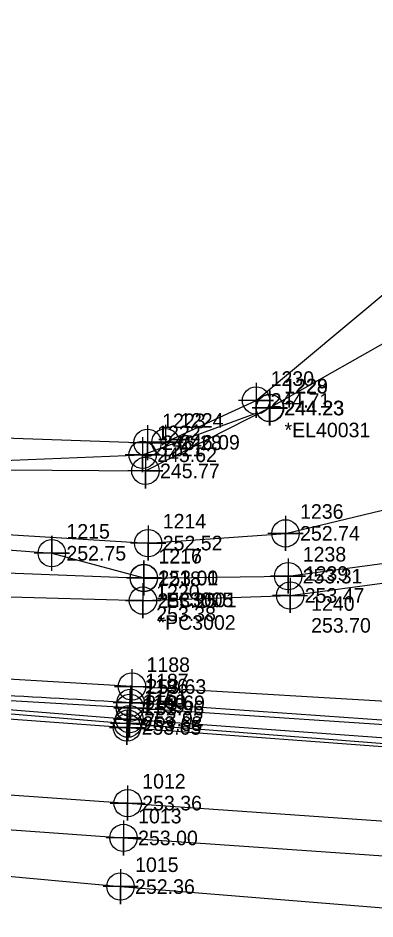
# Model space of a CAD drawing. Extents: x 2130962 to 2131465, y 643052 to 644206.
# Drawn here: x 2131077.2 to 2131138.3, y 643151.7 to 643306.2 of the extents above; entities that cross this region are included whole.
import ezdxf

# ---------------------------------------------------------------- set-up
doc = ezdxf.new("R2010")
doc.units = 0
for name, color, linetype in [('Exist DTM Breakline', 7, 'Continuous'), ('Exist DTM Breakline Cogo Elevation', 7, 'Continuous'), ('Exist DTM Breakline Cogo Number', 7, 'Continuous'), ('Exist DTM Breakline Cogo Point CELL', 7, 'Continuous'), ('Exist DTM Drainline', 7, 'Continuous'), ('Exist DTM Drainline Cogo Comment', 7, 'Continuous'), ('Exist DTM Drainline Cogo Elevation', 7, 'Continuous'), ('Exist DTM Drainline Cogo Number', 7, 'Continuous'), ('Exist DTM Drainline Cogo Point CELL', 7, 'Continuous'), ('Exist Roads Curbs', 7, 'Continuous'), ('Exist Roads Curbs Cogo Elevation', 7, 'Continuous'), ('Exist Roads Curbs Cogo Number', 7, 'Continuous'), ('Exist Roads Curbs Cogo Point CELL', 7, 'Continuous'), ('Exist Roads EOP', 7, 'Continuous'), ('Exist Roads EOP Cogo Comment', 7, 'Continuous'), ('Exist Roads EOP Cogo Elevation', 7, 'Continuous'), ('Exist Roads EOP Cogo Number', 7, 'Continuous'), ('Exist Roads EOP Cogo Point CELL', 7, 'Continuous'), ('Exist Roads EOT', 7, 'Continuous'), ('Exist Roads EOT Cogo Comment', 7, 'Continuous'), ('Exist Roads EOT Cogo Elevation', 7, 'Continuous'), ('Exist Roads EOT Cogo Number', 7, 'Continuous'), ('Exist Roads EOT Cogo Point CELL', 7, 'Continuous'), ('Exist Roads Soil', 7, 'Continuous'), ('Exist Roads Soil Cogo Comment', 7, 'Continuous'), ('Exist Roads Soil Cogo Elevation', 7, 'Continuous'), ('Exist Roads Soil Cogo Number', 7, 'Continuous'), ('Exist Roads Soil Cogo Point CELL', 7, 'Continuous')]:
    doc.layers.add(name, color=color, linetype=linetype)

msp = doc.modelspace()

# ---------------------------------------------------------------- linework, layer by layer
at = {"layer": 'Exist DTM Breakline'}
for points in [[(2131000.7408, 643235.0731), (2131050.2503, 643235.0771), (2131099.3971, 643233.3967), (2131102.4734, 643233.467), (2131117.9784, 643240.6457), (2131141.4902, 643260.2289), (2131148.9668, 643267.309), (2131161.3925, 643274.3195), (2131169.1458, 643283.2692), (2131172.0772, 643292.493), (2131174.434, 643316.7319), (2131174.0607, 643347.0813), (2131174.2633, 643367.3367), (2131180.4607, 643413.966), (2131183.0424, 643464.7744), (2131179.7562, 643510.5479), (2131157.5016, 643561.2065), (2131139.0887, 643604.6918), (2131124.996, 643650.6897)], [(2131000.2707, 643222.2884), (2131049.3172, 643219.2511), (2131099.5024, 643216.1866), (2131123.0232, 643217.8518), (2131146.7721, 643223.5416), (2131166.8509, 643229.4959), (2131199.4918, 643255.6512), (2131208.4065, 643272.9132), (2131217.3052, 643317.6851), (2131214.0619, 643367.4973), (2131211.0353, 643416.1836)], [(2130997.5489, 643165.941), (2131045.6664, 643161.7962), (2131094.7686, 643157.2786), (2131146.0902, 643153.1147), (2131194.5413, 643146.0346), (2131212.7846, 643137.5737), (2131227.5943, 643121.2545), (2131235.8712, 643098.3644), (2131243.3589, 643075.7514)]]:
    msp.add_lwpolyline(points, dxfattribs=at)
at = {"layer": 'Exist DTM Breakline Cogo Point CELL'}
for points in [[(2131117.9784, 643243.6457), (2131117.9784, 643237.6457), (2131117.9784, 643240.6457), (2131120.9784, 643240.6457), (2131114.9784, 643240.6457)], [(2131099.3971, 643236.3967), (2131099.3971, 643230.3967), (2131099.3971, 643233.3967), (2131102.3971, 643233.3967), (2131096.3971, 643233.3967)], [(2131102.4734, 643236.467), (2131102.4734, 643230.467), (2131102.4734, 643233.467), (2131105.4734, 643233.467), (2131099.4734, 643233.467)], [(2131123.0232, 643220.8518), (2131123.0232, 643214.8518), (2131123.0232, 643217.8518), (2131126.0232, 643217.8518), (2131120.0232, 643217.8518)], [(2131099.5024, 643219.1866), (2131099.5024, 643213.1866), (2131099.5024, 643216.1866), (2131102.5024, 643216.1866), (2131096.5024, 643216.1866)], [(2131094.7686, 643160.2786), (2131094.7686, 643154.2786), (2131094.7686, 643157.2786), (2131097.7686, 643157.2786), (2131091.7686, 643157.2786)]]:
    msp.add_lwpolyline(points, dxfattribs=at)
for centre in [(2131117.9784, 643240.6457), (2131099.3971, 643233.3967), (2131102.4734, 643233.467), (2131123.0232, 643217.8518), (2131099.5024, 643216.1866), (2131094.7686, 643157.2786)]:
    msp.add_circle(centre, 2.344, dxfattribs=at)
at = {"layer": 'Exist DTM Drainline'}
for points in [[(2131000.2029, 643226.7228), (2131050.9884, 643228.9032), (2131099.0297, 643228.5605), (2131120.2968, 643239.3591), (2131144.9156, 643253.3469), (2131146.4739, 643252.3674), (2131154.3188, 643256.8046), (2131168.9618, 643265.5132), (2131176.6257, 643272.964), (2131179.8144, 643285.303), (2131183.3842, 643315.022), (2131190.1471, 643365.8731), (2131190.1489, 643413.686), (2131192.3886, 643466.4632), (2131188.8083, 643512.615), (2131184.0059, 643563.7066), (2131175.3, 643610.7482), (2131168.3784, 643658.7431), (2131156.7476, 643707.4708), (2131144.9036, 643754.0458), (2131132.9438, 643802.544), (2131118.0831, 643847.9475), (2131104.0084, 643896.8663), (2131096.3866, 643919.4077)], [(2131000.2521, 643229.3945), (2131050.9247, 643229.3918), (2131098.5522, 643231.3283), (2131118.2949, 643238.5741)]]:
    msp.add_lwpolyline(points, dxfattribs=at)
at = {"layer": 'Exist DTM Drainline Cogo Point CELL'}
for points in [[(2131120.2968, 643242.3591), (2131120.2968, 643236.3591), (2131120.2968, 643239.3591), (2131123.2968, 643239.3591), (2131117.2968, 643239.3591)], [(2131120.3635, 643242.3333), (2131120.3635, 643236.3333), (2131120.3635, 643239.3333), (2131123.3635, 643239.3333), (2131117.3635, 643239.3333)], [(2131098.5522, 643234.3283), (2131098.5522, 643228.3283), (2131098.5522, 643231.3283), (2131101.5522, 643231.3283), (2131095.5522, 643231.3283)], [(2131099.0297, 643231.5605), (2131099.0297, 643225.5605), (2131099.0297, 643228.5605), (2131102.0297, 643228.5605), (2131096.0297, 643228.5605)]]:
    msp.add_lwpolyline(points, dxfattribs=at)
for centre in [(2131120.2968, 643239.3591), (2131120.3635, 643239.3333), (2131098.5522, 643231.3283), (2131099.0297, 643228.5605)]:
    msp.add_circle(centre, 2.344, dxfattribs=at)
at = {"layer": 'Exist Roads Curbs'}
for points in [[(2131198.0624, 643180.7236), (2131148.4553, 643184.4513), (2131096.3634, 643187.9153), (2131047.6348, 643190.8052), (2130998.9825, 643194.049), (2130985.1601, 643194.9243)], [(2130985.2008, 643194.5895), (2130998.8721, 643193.5705), (2131048.4066, 643189.8131), (2131096.2876, 643185.9927), (2131148.0156, 643182.2174), (2131198.038, 643178.5389), (2131226.4879, 643176.4123)]]:
    msp.add_lwpolyline(points, dxfattribs=at)
at = {"layer": 'Exist Roads Curbs Cogo Point CELL'}
for points in [[(2131096.3634, 643190.9153), (2131096.3634, 643184.9153), (2131096.3634, 643187.9153), (2131093.6334, 643187.9153), (2131099.3634, 643187.9153)], [(2131096.2876, 643188.9927), (2131096.2876, 643182.9927), (2131096.2876, 643185.9927), (2131093.5576, 643185.9927), (2131099.2876, 643185.9927)]]:
    msp.add_lwpolyline(points, dxfattribs=at)
for centre in [(2131096.3634, 643187.9153), (2131096.2876, 643185.9927)]:
    msp.add_circle(centre, 2.344, dxfattribs=at)
at = {"layer": 'Exist Roads EOP'}
for points in [[(2131123.476, 643210.5181), (2131148.0359, 643213.8558), (2131166.2495, 643216.6951)], [(2130999.387, 643215.4489), (2131048.8311, 643212.0849), (2131098.77, 643210.1813), (2131123.476, 643210.5181)], [(2130985.0681, 643194.3028), (2130998.8642, 643193.2032), (2131048.3641, 643189.1686), (2131096.0386, 643185.2243), (2131148.0312, 643181.1875), (2131197.8595, 643177.8797), (2131226.6095, 643175.7594)], [(2130997.2568, 643172.4279), (2131046.6093, 643169.1365), (2131095.2834, 643165.6174), (2131146.4463, 643162.1202), (2131188.4433, 643158.2198), (2131196.4033, 643155.8931)]]:
    msp.add_lwpolyline(points, dxfattribs=at)
for points in [[(2131166.2495, 643216.6951), (2131171.8131, 643218.7244), (2131182.3713, 643223.9726), (2131191.8117, 643231.1489), (2131200.5013, 643239.6993), (2131208.8071, 643249.0697), (2131216.0672, 643259.0032), (2131218.7188, 643264.347), (2131220.5363, 643270.0958), (2131222.8445, 643282.0077), (2131224.3583, 643293.9245), (2131224.8763, 643317.7904), (2131222.0632, 643367.6716), (2131218.5448, 643416.8114), (2131214.3187, 643466.3462), (2131209.1735, 643515.6666), (2131202.7939, 643565.1545), (2131195.0475, 643613.9937), (2131186.4014, 643662.4763), (2131176.0113, 643711.405), (2131164.6154, 643759.8896), (2131151.874, 643807.8526), (2131137.8554, 643855.4065), (2131122.5733, 643902.8574), (2131105.9622, 643949.4862), (2131091.5349, 643988.0437)], [(2131226.9097, 643179.1731), (2131198.0663, 643181.4699), (2131148.43, 643185.1482), (2131096.4958, 643188.7823), (2131047.6681, 643191.5278), (2130998.9471, 643194.464)]]:
    msp.add_spline(points, degree=3, dxfattribs=at)
at = {"layer": 'Exist Roads EOP Cogo Point CELL'}
for points in [[(2131123.476, 643213.5181), (2131123.476, 643207.5181), (2131123.476, 643210.5181), (2131126.476, 643210.5181), (2131120.476, 643210.5181)], [(2131098.77, 643213.1813), (2131098.77, 643207.1813), (2131098.77, 643210.1813), (2131101.77, 643210.1813), (2131095.77, 643210.1813)], [(2131096.4958, 643191.7823), (2131096.4958, 643185.7823), (2131096.4958, 643188.7823), (2131099.4958, 643188.7823), (2131093.4958, 643188.7823)], [(2131096.0386, 643188.2243), (2131096.0386, 643182.2243), (2131096.0386, 643185.2243), (2131099.0386, 643185.2243), (2131093.0386, 643185.2243)], [(2131095.2834, 643168.6174), (2131095.2834, 643162.6174), (2131095.2834, 643165.6174), (2131098.2834, 643165.6174), (2131092.2834, 643165.6174)]]:
    msp.add_lwpolyline(points, dxfattribs=at)
for centre in [(2131098.77, 643210.1813), (2131123.476, 643210.5181), (2131096.4958, 643188.7823), (2131096.0386, 643185.2243), (2131095.2834, 643165.6174)]:
    msp.add_circle(centre, 2.344, dxfattribs=at)
at = {"layer": 'Exist Roads EOT'}
for points in [[(2131123.8135, 643207.212), (2131148.5569, 643210.5345), (2131166.718, 643215.2083)], [(2130999.0837, 643210.149), (2131048.883, 643207.6861), (2131098.6093, 643206.3137), (2131123.8135, 643207.212)], [(2130984.5181, 643192.3513), (2130998.5672, 643191.5434), (2131048.4259, 643188.0549), (2131095.8768, 643184.5731), (2131148.0696, 643180.6818), (2131197.8229, 643176.9862), (2131227.4987, 643174.8043), (2131230.1348, 643175.616), (2131231.2992, 643177.7905), (2131229.0582, 643182.3901), (2131224.2697, 643184.0454), (2131198.1991, 643185.755), (2131149.0546, 643188.5149), (2131096.726, 643191.5809), (2131048.6064, 643194.4262), (2130999.1051, 643197.5379), (2130984.2748, 643198.4247)], [(2130997.5703, 643178.3518), (2131046.7671, 643175.0968), (2131095.9912, 643171.5914), (2131146.7075, 643168.0129), (2131169.9901, 643166.2046), (2131196.9631, 643160.4097)]]:
    msp.add_lwpolyline(points, dxfattribs=at)
msp.add_spline([(2131166.718, 643215.2083), (2131172.3866, 643217.1804), (2131211.4056, 643247.1499), (2131223.758, 643268.7314), (2131228.3848, 643317.935), (2131225.533, 643367.8628), (2131222.2486, 643417.1873), (2131217.9619, 643466.6275), (2131212.8794, 643516.2377), (2131206.5633, 643565.5764), (2131198.9021, 643614.6757), (2131189.6851, 643663.4055), (2131179.3985, 643712.1311), (2131168.3085, 643760.7185), (2131155.755, 643808.9129), (2131141.6748, 643856.5528), (2131126.5354, 643904.2758), (2131110.3559, 643951.0191), (2131092.4533, 643998.1348), (2131073.722, 644043.631), (2131053.1654, 644089.359), (2131032.0052, 644134.0908), (2131009.0644, 644179.3802)], degree=3, dxfattribs=at)
at = {"layer": 'Exist Roads EOT Cogo Point CELL'}
for points in [[(2131098.6093, 643209.3137), (2131098.6093, 643203.3137), (2131098.6093, 643206.3137), (2131095.6093, 643206.3137), (2131101.6093, 643206.3137)], [(2131123.8135, 643210.212), (2131123.8135, 643204.212), (2131123.8135, 643207.212), (2131120.8135, 643207.212), (2131126.8135, 643207.212)], [(2131096.726, 643194.5809), (2131096.726, 643188.5809), (2131096.726, 643191.5809), (2131093.726, 643191.5809), (2131099.726, 643191.5809)], [(2131095.8768, 643187.5731), (2131095.8768, 643181.5731), (2131095.8768, 643184.5731), (2131092.8768, 643184.5731), (2131098.8768, 643184.5731)], [(2131095.9912, 643174.5914), (2131095.9912, 643168.5914), (2131095.9912, 643171.5914), (2131092.9912, 643171.5914), (2131098.9912, 643171.5914)]]:
    msp.add_lwpolyline(points, dxfattribs=at)
for centre in [(2131123.8135, 643207.212), (2131098.6093, 643206.3137), (2131096.726, 643191.5809), (2131095.8768, 643184.5731), (2131095.9912, 643171.5914)]:
    msp.add_circle(centre, 2.344, dxfattribs=at)
at = {"layer": 'Exist Roads Soil'}
msp.add_lwpolyline([(2130999.7918, 643218.6269), (2131049.0553, 643217.0164), (2131083.0054, 643214.4454), (2131098.7667, 643210.2105)], dxfattribs=at)
at = {"layer": 'Exist Roads Soil Cogo Point CELL'}
for points in [[(2131083.0054, 643211.4454), (2131083.0054, 643217.4454), (2131083.0054, 643214.4454), (2131086.0054, 643214.4454), (2131080.0054, 643214.4454)], [(2131098.7667, 643207.2105), (2131098.7667, 643213.2105), (2131098.7667, 643210.2105), (2131101.7667, 643210.2105), (2131095.7667, 643210.2105)]]:
    msp.add_lwpolyline(points, dxfattribs=at)
for centre in [(2131083.0054, 643214.4454), (2131098.7667, 643210.2105)]:
    msp.add_circle(centre, 2.344, dxfattribs=at)

# ---------------------------------------------------------------- texts
at = {"layer": 'Exist DTM Breakline Cogo Elevation'}
for s, p in [('244.71', (2131120.4784, 643239.3957)), ('246.28', (2131101.8971, 643232.1467)), ('246.09', (2131104.9734, 643232.217)), ('252.74', (2131125.5232, 643216.6018)), ('252.52', (2131102.0024, 643214.9366)), ('252.36', (2131097.2686, 643156.0286))]:
    msp.add_text(s, height=2.5, dxfattribs=at).set_placement(p)
at = {"layer": 'Exist DTM Breakline Cogo Number'}
for s, p in [('1230', (2131120.4784, 643243.1457)), ('1223', (2131101.8971, 643235.8967)), ('1224', (2131104.9734, 643235.967)), ('1236', (2131125.5232, 643220.3518)), ('1214', (2131102.0024, 643218.6866)), ('1015', (2131097.2686, 643159.7786))]:
    msp.add_text(s, height=2.5, dxfattribs=at).set_placement(p)
at = {"layer": 'Exist DTM Drainline Cogo Comment'}
msp.add_text('*EL40031', height=2.5, dxfattribs=at).set_placement((2131122.8635, 643234.3333))
at = {"layer": 'Exist DTM Drainline Cogo Elevation'}
for s, p in [('244.23', (2131122.7968, 643238.1091)), ('244.23', (2131122.8635, 643238.0833)), ('245.62', (2131101.0522, 643230.0783)), ('245.77', (2131101.5297, 643227.3105))]:
    msp.add_text(s, height=2.5, dxfattribs=at).set_placement(p)
at = {"layer": 'Exist DTM Drainline Cogo Number'}
for s, p in [('1228', (2131122.7968, 643241.8591)), ('1229', (2131122.8635, 643241.8333)), ('1222', (2131101.0522, 643233.8283)), ('1221', (2131101.5297, 643231.0605))]:
    msp.add_text(s, height=2.5, dxfattribs=at).set_placement(p)
at = {"layer": 'Exist Roads Curbs Cogo Elevation'}
for s, p in [('253.96', (2131098.8634, 643186.6653)), ('253.92', (2131098.7876, 643184.7427))]:
    msp.add_text(s, height=2.5, dxfattribs=at).set_placement(p)
at = {"layer": 'Exist Roads Curbs Cogo Number'}
for s, p in [('1186', (2131098.8634, 643190.4153)), ('1161', (2131098.7876, 643188.4927))]:
    msp.add_text(s, height=2.5, dxfattribs=at).set_placement(p)
at = {"layer": 'Exist Roads EOP Cogo Comment'}
msp.add_text('*PC3001', height=2.5, dxfattribs=at).set_placement((2131101.27, 643205.1813))
at = {"layer": 'Exist Roads EOP Cogo Elevation'}
for s, p in [('253.01', (2131101.27, 643208.9313)), ('253.31', (2131125.976, 643209.2681)), ('253.69', (2131098.9958, 643187.5323)), ('253.68', (2131098.5386, 643183.9743)), ('253.00', (2131097.7834, 643164.3674))]:
    msp.add_text(s, height=2.5, dxfattribs=at).set_placement(p)
at = {"layer": 'Exist Roads EOP Cogo Number'}
for s, p in [('1217', (2131101.27, 643212.6813)), ('1238', (2131125.976, 643213.0181)), ('1187', (2131098.9958, 643191.2823)), ('1160', (2131098.5386, 643187.7243)), ('1013', (2131097.7834, 643168.1174))]:
    msp.add_text(s, height=2.5, dxfattribs=at).set_placement(p)
at = {"layer": 'Exist Roads EOT Cogo Comment'}
msp.add_text('*PC3002', height=2.5, dxfattribs=at).set_placement((2131101.1093, 643201.3137))
at = {"layer": 'Exist Roads EOT Cogo Elevation'}
for s, p in [('253.25', (2131101.1093, 643205.0637)), ('253.47', (2131126.3135, 643205.962)), ('253.38', (2131100.8845, 643202.7992)), ('253.70', (2131127.4167, 643200.822)), ('253.63', (2131099.226, 643190.3309)), ('253.65', (2131098.3768, 643183.3231)), ('253.36', (2131098.4912, 643170.3414))]:
    msp.add_text(s, height=2.5, dxfattribs=at).set_placement(p)
at = {"layer": 'Exist Roads EOT Cogo Number'}
for s, p in [('1239', (2131126.3135, 643209.712)), ('1218', (2131101.1093, 643208.8137)), ('1220', (2131100.8845, 643206.5492)), ('1240', (2131127.4167, 643204.572)), ('1188', (2131099.226, 643194.0809)), ('1159', (2131098.3768, 643187.0731)), ('1012', (2131098.4912, 643174.0914))]:
    msp.add_text(s, height=2.5, dxfattribs=at).set_placement(p)
at = {"layer": 'Exist Roads Soil Cogo Comment'}
msp.add_text('*EL3005', height=2.5, dxfattribs=at).set_placement((2131101.2667, 643205.2105))
at = {"layer": 'Exist Roads Soil Cogo Elevation'}
for s, p in [('252.75', (2131085.5054, 643213.1954)), ('253.00', (2131101.2667, 643208.9605))]:
    msp.add_text(s, height=2.5, dxfattribs=at).set_placement(p)
at = {"layer": 'Exist Roads Soil Cogo Number'}
for s, p in [('1215', (2131085.5054, 643216.9454)), ('1216', (2131101.2667, 643212.7105))]:
    msp.add_text(s, height=2.5, dxfattribs=at).set_placement(p)

doc.saveas('drawing.dxf')
